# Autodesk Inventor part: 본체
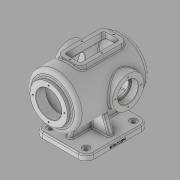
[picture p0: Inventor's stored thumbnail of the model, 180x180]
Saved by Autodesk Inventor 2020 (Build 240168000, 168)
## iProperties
Created: 2021-11
Part Number: 본체
Material: 일반
Document SubType Name: Modeling
Designer: Administrator
Density: 1 g/cm^3
Appearance: 기본값
Author: Administrator
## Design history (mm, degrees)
sketch "스케치1"
  geometry: L1 (-80, -65)-(80, -65); L2 (80, -65)-(80, 65); L3 (80, 65)-(-80, 65); L4 (-80, 65)-(-80, -65); L5 (-80, -65)-(80, 65); L6 (80, -65)-(-80, 65); 1 further point
  constraints: 12 end point, 2 midpoint, 2 parallel, 1 horizontal, 1 perpendicular
  dimensions: "d0" = 160 distance of L2.end L3.end; "d1" = 130 distance of L3.end L1.start
extrude "돌출1" new body sketch "스케치1" distance "d2" = 14; taper "d3" = 0 deg
fillet "모깎기1" dims "d4" = 20
sketch "스케치2"
  geometry: L1 (-60, -65)-(60, -65) reference; L2 (80, -45)-(80, 45) reference; L3 (60, 65)-(-60, 65) reference; L4 (-80, 45)-(-80, -45) reference; A1 r 20 centre (-60, -45) between (-80, -45) and (-60, -65) reference; A2 r 20 centre (60, -45) between (60, -65) and (80, -45) reference; A3 r 20 centre (60, 45) between (80, 45) and (60, 65) reference; A4 r 20 centre (-60, 45) between (-60, 65) and (-80, 45) reference; 5 further points
  constraints: 4 coincident
hole "구멍1" sketch "스케치2" at (-60, 45), (-60, -45), (60, -45), (60, 45) diameter "d5" = 9; stored, may be unused: countersink angle "d9" = 90 deg, drill point angle "d11" = 0 deg; dims "d6" = 24, "d7" = 18, "d8" = 2, "d10" = 8
sketch "스케치3"
  geometry: L1 (-100, 114)-(100, 114); L2 (100, 114)-(100, 179); L3 (100, 179)-(-75.993, 179); L4 (80, 0)-(80, 14) reference; L5 (-71.239, 169)-(85, 169); L6 (100, 146.5)-(85, 146.5); L7 (85, 146.5)-(85, 169); A1 r 100 centre (0, 114) between (-75.993, 179) and (-100, 114); A2 r 90 centre (0, 114) between (-71.239, 169) and (-90, 114); 1 further point
  constraints: 12 end point, 4 point on circle, 2 centre point, 2 horizontal, 1 horizontal alignment, 1 midpoint, 1 perpendicular, 1 point on line, 1 vertical
  dimensions: "d12" = 114 vertical distance of point (0, 0) L1.end; "d13" = 20 distance from line of L4 L1.end; "d14" = 130 diameter of L3 L1; "d15" = 100 radius of A1; "d16" = 200 distance of L1.start L1.end; "d19" = 10 radial gap between concentric circles of A1 A2; "d20" = 65 diameter of L6 L1; "d21" = 15 distance of L6.start L6.end; "d22" = 110 diameter of L5 L1
revolve "회전1" stored, may be unused: angle "d18" = 90 deg
revolve "회전2" stored, may be unused: angle "d23" = 90 deg
sketch "스케치4"
  geometry: C1 r 32.5 at (0, 0) reference; C2 r 47.5 at (0, 0); 1 further point
  constraints: 1 centre point, 1 coincident
  dimensions: "d24" = 95 diameter of C2
extrude "돌출2" join sketch "스케치4" distance "d25" = 10; taper "d26" = 0 deg
sketch "스케치5"
  geometry: C1 r 47.5 at (0, 0) reference; C2 r 32.5 at (0, 0); 1 further point
  constraints: 1 centre point, 1 coincident
  dimensions: "d27" = 65 diameter of C2
extrude "돌출3" cut sketch "스케치5" distance "d28" = 20; taper "d29" = 0 deg
node "작업 평면1"
sketch "스케치6"
  geometry: L1 (-60, 30)-(60, 30); L2 (60, 30)-(60, -30); L3 (60, -30)-(-60, -30); L4 (-60, -30)-(-60, 30); L5 (-110, 47.5)-(-110, -47.5) reference; 2 further points
  constraints: 8 end point, 2 parallel, 1 horizontal, 1 horizontal alignment, 1 midpoint, 1 perpendicular
  dimensions: "d31" = 50 distance between parallel lines of L5 L4; "d32" = 120 distance of L1.start L1.end; "d33" = 60 distance of L1.end L2.end
extrude "돌출4" join sketch "스케치6" stored distance "d34" = 20; taper "d35" = 0 deg
fillet "모깎기2" dims "d36" = 15
sketch "스케치7"
  geometry: L1 (-50, 20)-(50, 20); L2 (50, 20)-(50, -20); L3 (50, -20)-(-50, -20); L4 (-50, -20)-(-50, 20); L5 (-50, 20)-(50, -20); L6 (50, 20)-(-50, -20); L7 (60, -15)-(60, 15) reference; L8 (-45, -30)-(45, -30) reference; 1 further point
  constraints: 12 end point, 2 midpoint, 2 parallel, 1 horizontal, 1 perpendicular
  dimensions: "d37" = 10 distance between parallel lines of L7 L2; "d38" = 10 distance between parallel lines of L8 L3
extrude "돌출5" cut sketch "스케치7" distance "d39" = 20; taper "d40" = 0 deg
fillet "모깎기3" dims "d41" = 5
sketch "스케치8"
  geometry: 5 further points
  constraints: 2 horizontal alignment, 2 vertical alignment
  dimensions: "d42" = 50 distance of point (0, 25) point (0, -25); "d43" = 25 distance of point (0, 0) point (0, -25); "d44" = 55 distance of point (0, 0) point (55, 0); "d45" = 55 distance of point (0, 0) point (-55, 0)
hole "구멍2" sketch "스케치8" at (0, 25), (0, -25), (-55, 0), (55, 0) diameter "d46" = 3.242; stored, may be unused: countersink angle "d50" = 90 deg, drill point angle "d52" = 118 deg; dims "d47" = 9, "d48" = 18, "d49" = 2, "d51" = 11
node "작업 평면2"
sketch "스케치9"
  geometry: L1 (110, 66.5)-(110, 161.5) reference; L2 (-45, 184)-(45, 184) reference; C1 r 40 at (-17, 114); 1 further point
  constraints: 1 centre point
  dimensions: "d54" = 80 diameter of C1; "d87" = 127 distance from line of L1 C1.centre; "d88" = 70 distance from line of L2 C1.centre
extrude "돌출6" join sketch "스케치9" stored distance "d56" = 20; taper "d57" = 0 deg
sketch "스케치10"
  geometry: C1 r 40 at (0, 0) reference; 2 further points
  constraints: 1 coincident
hole "구멍3" sketch "스케치10" at (0, 0) diameter "d58" = 42; stored, may be unused: countersink angle "d62" = 90 deg, drill point angle "d64" = 118 deg; dims "d59" = 9, "d60" = 52, "d61" = 18, "d63" = 25
sketch "스케치11" dims "d65" = 65
  geometry: L1 (0, 0)-(0, -32.5); C1 r 40 at (0, 0) reference; 2 further points
  constraints: 2 coincident, 2 end point, 1 vertical, 1 vertical alignment, 2 other
hole "구멍4" sketch "스케치11" at (0, -32.5) diameter "d66" = 3.242; stored, may be unused: countersink angle "d70" = 90 deg, drill point angle "d72" = 118 deg; dims "d67" = 11, "d68" = 52, "d69" = 18, "d71" = 13
sketch "스케치12" dims "d76" = 80
  geometry: L1 (0, 0)-(40, 0); C1 r 47.5 at (0, 0) reference; 2 further points
  constraints: 2 coincident, 2 end point, 1 horizontal, 1 horizontal alignment, 2 other
hole "구멍5" sketch "스케치12" at (40, 0) diameter "d77" = 3.242; stored, may be unused: countersink angle "d81" = 90 deg, drill point angle "d83" = 118 deg; dims "d78" = 11, "d79" = 52, "d80" = 18, "d82" = 13
sketch "스케치13"
  geometry: L1 (-45, 0)-(45, 0) reference; L2 (-45, 14)-(45, 14) reference; L3 (-36, 12)-(-54, 12) reference; L4 (-45, 14)-(-65, 14) reference; L5 (-65, 14)-(-65, 0) reference; L6 (-65, 0)-(-45, 0) reference; L7 (-45, 0)-(-45, 14) reference; L8 (-65, 14)-(-45, 14) reference; L9 (45, 14)-(45, 0) reference; L10 (-45, 14)-(45, 14) reference; L11 (-45, 0)-(-45, 14) reference; L12 (-45, 0)-(45, 0) reference; L13 (50, 14)-(38.594, 45.337); L14 (-50, 14)-(-38.849, 44.638); L15 (65, 0)-(65, 14) reference; 1 further point
  constraints: 4 end point, 2 point on line
  dimensions: "d90" = 100 distance of L14.start L13.start; "d91" = 70 deg angle of L2 L13; "d92" = 70 deg angle of L4 L14; "d93" = 15 distance from line of L13.start L15
  node "투영된 루프3"
  node "투영된 루프4"
sketch "스케치14"
  geometry: L1 (-7, 7)-(7, 7); L2 (7, 7)-(7, -7); L3 (7, -7)-(-7, -7); L4 (-7, -7)-(-7, 7); L5 (-7, 7)-(7, -7); L6 (7, 7)-(-7, -7); 1 further point
  constraints: 12 end point, 2 midpoint, 2 parallel, 1 horizontal, 1 perpendicular
  dimensions: "d94" = 14 distance of L1.end L2.end; "d95" = 14 distance of L2.end L3.end
extrude "돌출7" join sketch "스케치14" stored distance "d96" = 20; taper "d97" = 0 deg
feature "리브1" dims "d98" = 1, "d99" = 14, "d100" = 0, "d101" = 0, "d102" = 1, "d103" = 1
feature "리브2" dims "d104" = 1, "d105" = 14, "d106" = 0, "d107" = 0, "d108" = 1, "d109" = 1
sketch "스케치15"
  geometry: L1 (51, 14)-(69, 14) reference; L2 (-60, 14)-(60, 14) reference; L3 (80, 0)-(60, 0) reference; L4 (-60, 0)-(-80, 0) reference; L5 (60, 14)-(51.905, 36.24); L6 (-60, 14)-(-51.193, 38.198); L7 (80, 0)-(80, 14) reference; 1 further point
  constraints: 4 end point, 1 midpoint, 1 point on line
  dimensions: "d110" = 70 deg angle of L2 L5; "d111" = 70 deg angle of L2 L6; "d112" = 120 distance of L6.start L5.start; "d113" = 20 distance from line of L5.start L7
feature "리브3" dims "d114" = 1, "d115" = 14, "d116" = 0, "d117" = 0, "d118" = 1, "d119" = 1
feature "리브4" dims "d120" = 1, "d121" = 14, "d122" = 0, "d123" = 0, "d124" = 1, "d125" = 1
fillet "모깎기4" dims "d126" = 3
fillet "모깎기5" dims "d127" = 3
fillet "모깎기6" dims "d128" = 3
fillet "모깎기7" dims "d129" = 3
fillet "모깎기8" dims "d130" = 3
fillet "모깎기9" dims "d131" = 10
fillet "모깎기10" dims "d132" = 3
fillet "모깎기11" dims "d133" = 0.3
fillet "모깎기12" dims "d134" = 3
chamfer "모따기1" distance "d135" = 1; stored, may be unused: second distance "d136" = 2, angle "d137" = 45 deg
sketch "스케치16"
  geometry: L1 (39.261, 8.002)-(80.739, 8.002); L2 (80.739, 8.002)-(80.739, 1.998); L3 (80.739, 1.998)-(39.261, 1.998); L4 (39.261, 1.998)-(39.261, 8.002); L5 (39.261, 1.998)-(80.739, 8.002); L6 (0, 0)-(120, 0) reference; 3 further points
  constraints: 2 end point, 2 midpoint, 1 vertical alignment, 2 other
  dimensions: "d138" = 5 distance of point (60, 0) point (60, 5)
feature "엠보싱1" sketch "스케치16" dims "d139" = 0.5, "d140" = 0
fillet "모깎기13" dims "d141" = 3
node "솔리드1"
pattern_circular "원형 패턴1" dims angle "d74" = 360 deg
mirror "미러1"
pattern_circular "원형 패턴2" dims angle "d85" = 360 deg
node "투영된 루프1"
node "투영된 루프2"
feature "A9D066F2-1C7D-4E18-AEED-F7BC21143FA4" dims "d5" = 9, "d6" = 24, "d7" = 18, "d8" = 2, "d9" = 90 deg, "d10" = 8, "d11" = 0
other parameters: "d30" = 184, "d53" = 75
